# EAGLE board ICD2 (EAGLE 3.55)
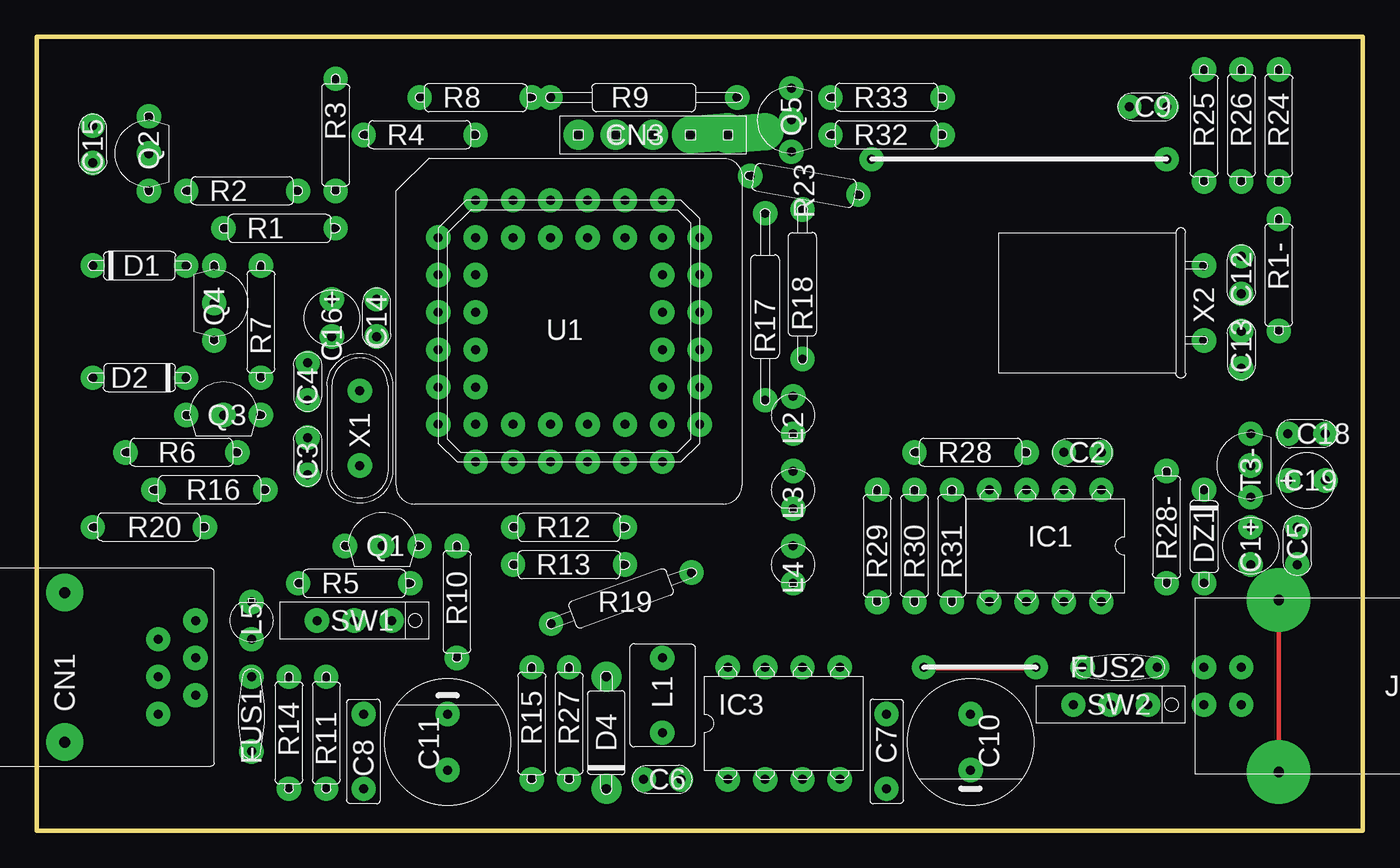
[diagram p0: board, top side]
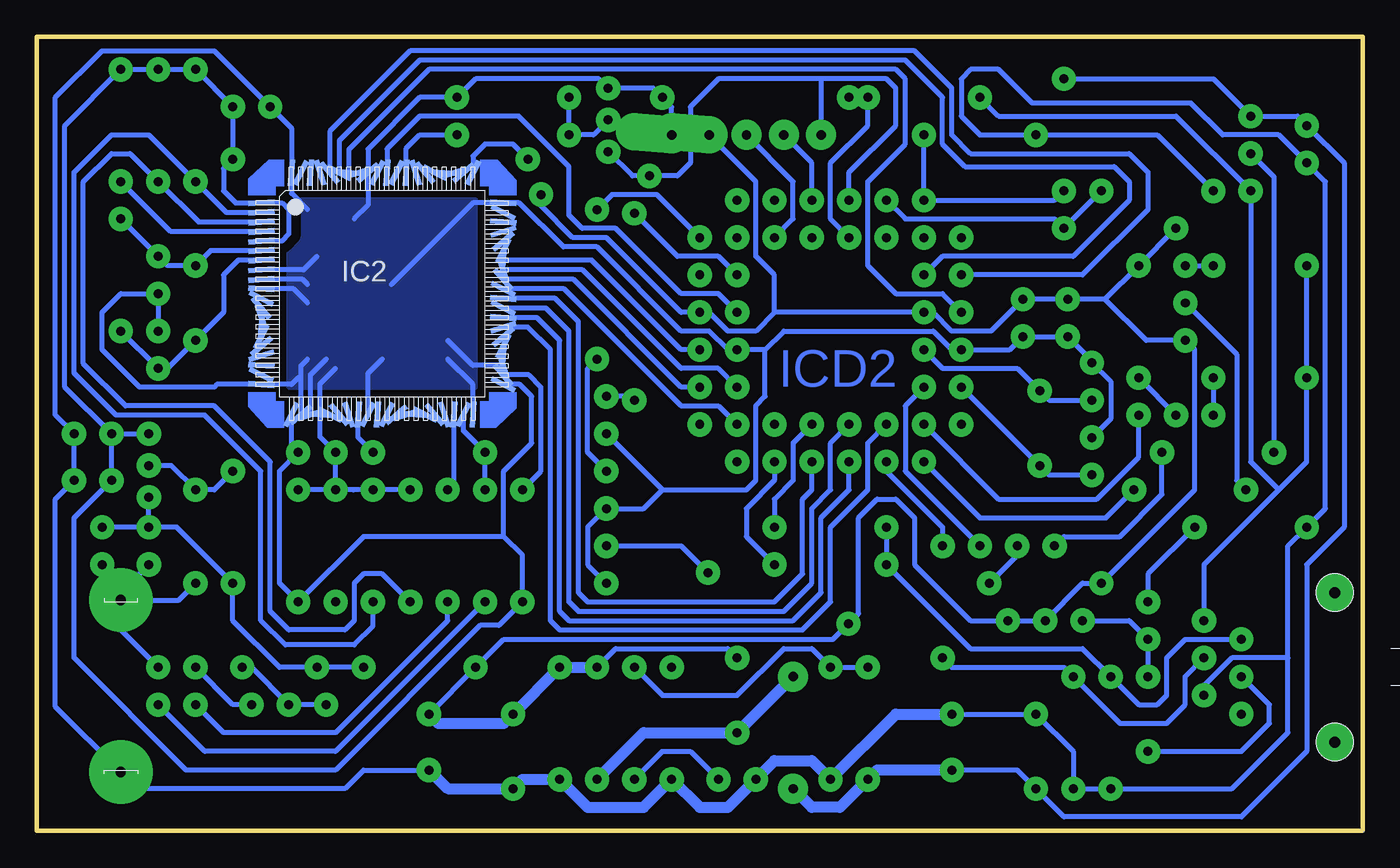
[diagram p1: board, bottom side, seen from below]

Size 90.17 x 53.98 mm. Coordinates in mm from the lower left corner, seen from the top.
Outline: 0,0 0,53.98 90.17,53.98 90.17,0 0,0
Copper layers used: COTE_COM, COTE_SOU

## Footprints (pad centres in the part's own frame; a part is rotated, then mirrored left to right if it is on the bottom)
-2,5-G = drill 0.612 pad 1.651 round:  -1.27,0;  1.27,0
2,5-0 = drill 0.612 pad 1.651 round:  -1.27,0;  1.27,0
5 = drill 0.612 pad 1.651 round:  2.54,0;  -2.54,0
-08-00 = drill 0.612 pad 1.651 round:  -1.905,0;  1.905,0
DUL-6 = drill 0.612 pad 1.651 round:  -1.27,-0.635;  1.27,0.635;  -1.27,1.905;  1.27,3.175;  1.27,-1.905;  -1.27,-3.175 | drill 0.744 pad 2.54 round:  7.62,-5.08;  7.62,5.08
14-05 = drill 0.637 pad 2.032 round:  -3.81,0;  -1.27,0;  1.27,0 | drill 0.637 pad 2.54 offset:  3.81,0;  6.35,0
6,3 = drill 0.612 pad 1.651 round:  3.175,0;  -3.175,0
7,5-1 = drill 0.637 pad 2.032 round:  -3.81,0;  3.81,0
SE-5 = drill 0.612 pad 1.651 round:  -2.54,0;  2.54,0
L-08 = drill 0.612 pad 1.651 round:  0,0;  2.54,0;  5.08,0;  7.62,0;  7.62,7.62;  5.08,7.62;  2.54,7.62;  0,7.62
FP-80 = smd 1.778 x 0.356 rotated 4.8:  -8.223,2.275 | smd 1.778 x 0.356 rotated 4.3:  -8.223,6.175;  -8.223,0.325 | smd 1.778 x 0.356 rotated 4.4:  -8.223,5.525;  -8.223,-6.175 | smd 1.778 x 0.356 rotated 4.5:  -8.223,4.875 | smd 1.778 x 0.356 rotated 4.6:  -8.223,4.225 | smd 1.778 x 0.356 rotated 4.7:  -8.223,3.575;  -8.223,2.925;  8.223,-0.325;  8.223,6.175 | smd 1.778 x 0.356 rotated 4.9:  -8.223,1.625 | smd 1.778 x 0.356 rotated 5:  -8.223,0.975 | smd 1.778 x 0.356 rotated 26.8:  -8.223,-0.325 | smd 1.778 x 0.356 rotated 49.3:  -8.223,-0.975 | smd 1.778 x 0.356 rotated 71.8:  -8.223,-1.625 | smd 1.778 x 0.356 rotated 94.3:  -8.223,-2.275 | smd 1.778 x 0.356 rotated 116.8:  -8.223,-2.925 | smd 1.778 x 0.356 rotated 139.3:  -8.223,-3.575 | smd 1.778 x 0.356 rotated 161.8:  -8.223,-4.225 | smd 1.778 x 0.356 rotated 184.3:  -8.223,-4.875 | smd 1.778 x 0.356 rotated 206.8:  -8.223,-5.525 | smd 0.356 x 1.778 rotated 26.9:  -6.175,-8.223 | smd 0.356 x 1.778 rotated 49.4:  -5.525,-8.223 | smd 0.356 x 1.778 rotated 71.9:  -4.875,-8.223 | smd 0.356 x 1.778 rotated 94.4:  -4.225,-8.223 | smd 0.356 x 1.778 rotated 116.9:  -3.575,-8.223 | smd 0.356 x 1.778 rotated 139.4:  -2.925,-8.223 | smd 0.356 x 1.778 rotated 161.9:  -2.275,-8.223 | smd 0.356 x 1.778 rotated 184.4:  -1.625,-8.223 | smd 0.356 x 1.778 rotated 206.9:  -0.975,-8.223 | smd 0.356 x 1.778 rotated 4.5:  -0.325,-8.223 | smd 0.356 x 1.778 rotated 27:  0.325,-8.223 | smd 0.356 x 1.778 rotated 49.5:  0.975,-8.223 | smd 0.356 x 1.778 rotated 72:  1.625,-8.223 | smd 0.356 x 1.778 rotated 94.5:  2.275,-8.223 | smd 0.356 x 1.778 rotated 117:  2.925,-8.223 | smd 0.356 x 1.778 rotated 139.5:  3.575,-8.223 | smd 0.356 x 1.778 rotated 162:  4.225,-8.223 | smd 0.356 x 1.778 rotated 184.5:  4.875,-8.223 | smd 0.356 x 1.778 rotated 207:  5.525,-8.223 | smd 0.356 x 1.778 rotated 4.6:  6.175,-8.223 | smd 1.778 x 0.356 rotated 27.1:  8.223,-6.175 | smd 1.778 x 0.356 rotated 49.6:  8.223,-5.525 | smd 1.778 x 0.356 rotated 72.1:  8.223,-4.875 | smd 1.778 x 0.356 rotated 94.6:  8.223,-4.225 | smd 1.778 x 0.356 rotated 117.1:  8.223,-3.575 | smd 1.778 x 0.356 rotated 139.6:  8.223,-2.925 | smd 1.778 x 0.356 rotated 162.1:  8.223,-2.275 | smd 1.778 x 0.356 rotated 184.6:  8.223,-1.625 | smd 1.778 x 0.356 rotated 207.1:  8.223,-0.975 | smd 1.778 x 0.356 rotated 27.2:  8.223,0.325 | smd 1.778 x 0.356 rotated 49.7:  8.223,0.975 | smd 1.778 x 0.356 rotated 72.2:  8.223,1.625 | smd 1.778 x 0.356 rotated 94.7:  8.223,2.275 | smd 1.778 x 0.356 rotated 117.2:  8.223,2.925 | smd 1.778 x 0.356 rotated 139.7:  8.223,3.575 | smd 1.778 x 0.356 rotated 162.2:  8.223,4.225 | smd 1.778 x 0.356 rotated 184.7:  8.223,4.875 | smd 1.778 x 0.356 rotated 207.2:  8.223,5.525 | smd 0.356 x 1.778 rotated 27.2:  6.175,8.223 | smd 0.356 x 1.778 rotated 49.7:  5.525,8.223 | smd 0.356 x 1.778 rotated 72.2:  4.875,8.223 | smd 0.356 x 1.778 rotated 94.7:  4.225,8.223 | smd 0.356 x 1.778 rotated 117.2:  3.575,8.223 | smd 0.356 x 1.778 rotated 139.7:  2.925,8.223 | smd 0.356 x 1.778 rotated 162.2:  2.275,8.223 | smd 0.356 x 1.778 rotated 184.7:  1.625,8.223 | smd 0.356 x 1.778 rotated 207.2:  0.975,8.223 | smd 0.356 x 1.778 rotated 4.8:  0.325,8.223 | smd 0.356 x 1.778 rotated 27.3:  -0.325,8.223 | smd 0.356 x 1.778 rotated 49.8:  -0.975,8.223 | smd 0.356 x 1.778 rotated 72.3:  -1.625,8.223 | smd 0.356 x 1.778 rotated 94.8:  -2.275,8.223 | smd 0.356 x 1.778 rotated 117.3:  -2.925,8.223 | smd 0.356 x 1.778 rotated 139.8:  -3.575,8.223 | smd 0.356 x 1.778 rotated 162.3:  -4.225,8.223 | smd 0.356 x 1.778 rotated 184.8:  -4.875,8.223 | smd 0.356 x 1.778 rotated 207.3:  -5.525,8.223 | smd 0.356 x 1.778 rotated 4.9:  -6.175,8.223
B-B2 = drill 0.612 pad 1.651 round:  -1.27,-1.27;  -1.27,1.27;  1.27,-1.27;  1.27,1.27 | drill 0.691 pad 4.318 round:  -3.81,-5.842;  -3.81,5.842
220æH = drill 0.612 pad 1.651 round:  -2.54,0;  2.54,0
D-3 = drill 0.612 pad 1.651 round:  -1.27,0;  1.27,0
D-3SF0 = drill 0.612 pad 1.651 round:  -1.27,0;  1.27,0
92 = drill 0.612 pad 1.651 round:  0,0;  2.54,0;  -2.54,0
 = drill 0.612 pad 1.651 round:  2.159,0;  -2.159,0;  0,0
10-7S = drill 0.612 pad 1.651 round:  -3.81,0;  3.81,0
10-12S = drill 0.612 pad 1.651 round:  6.35,0;  -6.35,0
10 = drill 0.612 pad 1.651 round:  5.08,0;  -5.08,0
ø0#R-1 = drill 0.612 pad 1.651 round:  4.774,1.738;  -4.774,-1.738
ø0#R-1' = drill 0.612 pad 1.651 round:  -0.635,-3.683;  0.635,3.683
-SIL3V = drill 0.612 pad 1.651 round:  0,0;  0,-2.54;  0,2.54
CC-44 = drill 0.612 pad 1.651 round:  2.54,-2.54;  0,-2.54;  7.62,-2.54;  5.08,-2.54;  12.7,-2.54;  10.16,-2.54;  17.78,-2.54;  15.24,-2.54;  15.24,0;  12.7,0;  10.16,0;  7.62,0;  5.08,0;  2.54,0;  2.54,-5.08;  0,-5.08;  2.54,-7.62;  0,-7.62;  2.54,-10.16;  0,-10.16;  2.54,-12.7;  0,-12.7;  2.54,-15.24;  0,-15.24;  7.62,-15.24;  5.08,-15.24;  5.08,-17.78;  2.54,-17.78;  10.16,-17.78;  7.62,-17.78;  12.7,-15.24;  10.16,-15.24;  15.24,-17.78;  12.7,-17.78;  17.78,-15.24;  15.24,-15.24;  17.78,-12.7;  15.24,-12.7;  17.78,-10.16;  15.24,-10.16;  17.78,-7.62;  15.24,-7.62;  17.78,-5.08;  15.24,-5.08
ARTZ = drill 0.612 pad 1.651 round:  -2.54,0;  2.54,0
ARTZ-C = drill 0.612 pad 1.651 round:  2.54,0;  -2.54,0

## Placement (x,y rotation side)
C1  10æ  [-2,5-G]  82.55,19.37 270 top
C2  104  [2,5-0]  71.12,25.72 180 top
C3  22p  [2,5-0]  18.41,25.46 90 top
C4  22p  [2,5-0]  18.41,30.54 90 top
C5  104  [2,5-0]  85.72,19.37 270 top
C6  47p  [2,5-0]  42.55,3.49 180 top
C7  1æ  [5]  57.78,5.4 270 top
C8  1æ  [5]  22.23,5.4 90 top
C9  104  [2,5-0]  75.56,49.21 180 top
C10  220æ  [-08-00]  63.5,6.03 270 top
C11  470æ/16V  [-08-00]  27.94,6.03 90 top
C12  22p  [2,5-0]  81.91,37.78 270 top
C13  22p  [2,5-0]  81.91,32.7 90 top
C14  104  [2,5-0]  23.11,34.86 270 top
C15  104  [2,5-0]  3.81,46.67 270 top
C16  10æ  [-2,5-G]  20.07,34.86 270 top
C18  104  [2,5-0]  86.36,26.99 0 top
C19  10æ  [-2,5-G]  86.36,23.81 0 top
CN1  ISP  [DUL-6]  9.52,11.11 180 top
CN3  PROG  [14-05]  40.64,47.31 0 top
D1  BAT85  [6,3]  6.98,38.42 0 top
D2  BAT85  [6,3]  6.98,30.8 180 top
D4  BYV  [7,5-1]  38.73,6.67 90 top
DZ1  3V9  [6,3]  79.38,20 270 top
FUS1  100mA  [SE-5]  14.61,7.94 270 top
FUS2  200mA  [SE-5]  73.66,11.11 180 top
IC1  24LC16  [L-08]  72.39,23.18 180 top
IC2  CY7C64613  [FP-80]  66.67,36.51 0 bottom
IC3  MAX630  [L-08]  46.99,3.49 0 top
J4  USB  [B-B2]  80.65,9.84 180 top
L1  470æ  [220æH]  42.55,9.21 270 top
L2  FAIL  [D-3]  51.44,28.26 90 top
L3  RUN  [D-3]  51.44,23.18 90 top
L4  ON  [D-3]  51.44,18.1 90 top
L5  ISP  [D-3SF0]  14.61,14.29 270 top
Q1  547  [92]  23.5,19.37 0 top
Q2  557  [92]  7.62,46.04 90 top
Q3  547  [92]  12.7,28.26 0 top
Q4  557  [92]  12.06,35.88 270 top
Q5  547  []  51.31,48.32 90 top
R1  4K7  [10-7S]  16.51,40.96 0 top
R1-  1M  [10-7S]  84.45,37.78 270 top
R2  4K7  [10-7S]  13.97,43.5 180 top
R3  6K8  [10-7S]  20.32,47.31 270 top
R4  2K2  [10-7S]  26.04,47.31 180 top
R5  100K  [10-7S]  21.59,16.83 0 top
R6  47K  [10-7S]  9.84,25.72 180 top
R7  22K  [10-7S]  15.24,34.61 270 top
R8  6K8  [10-7S]  29.84,49.85 0 top
R9  2K2  [10-12S]  41.27,49.85 0 top
R10  330R  [10-7S]  28.57,15.56 270 top
R11  4K7  [10-7S]  19.69,6.67 270 top
R12  330R  [10-7S]  36.2,20.64 0 top
R13  330R  [10-7S]  36.2,18.1 0 top
R14  4K7  [10-7S]  17.14,6.67 270 top
R15  137K  [10-7S]  33.66,7.3 270 top
R16  22K  [10-7S]  11.75,23.18 180 top
R17  1K5  [10-12S]  49.53,35.62 90 top
R18  1K5  [10]  52.07,37.15 90 top
R19  1K5  [ø0#R-1]  39.75,15.81 0 top
R20  75R  [10-7S]  7.62,20.64 180 top
R23  10K  [ø0#R-1']  52.2,43.88 90 top
R24  10K  [10-7S]  84.45,47.94 270 top
R25  1K  [10-7S]  79.38,47.94 270 top
R26  1K  [10-7S]  81.91,47.94 270 top
R27  15K  [10-7S]  36.2,7.3 270 top
R28  1K5  [10-7S]  63.5,25.72 180 top
R28-  150R  [10-7S]  76.84,20.64 90 top
R29  10K  [10-7S]  57.15,19.37 270 top
R30  22R  [10-7S]  59.69,19.37 90 top
R31  22R  [10-7S]  62.23,19.37 90 top
R32  1K  [10-7S]  57.78,47.31 180 top
R33  4K7  [10-7S]  57.78,49.85 180 top
SW1  PWR  [-SIL3V]  21.59,14.29 90 top
SW2  USB  [-SIL3V]  73.03,8.57 90 top
T3-  547  []  82.55,24.83 90 top
U1  PIC16F877-L  [CC-44]  27.3,42.86 0 top
U$7  [ILAND]  22.86,26.99 0 top
U$8  [ILAND]  67.31,26.99 180 top
X1  20M  [ARTZ]  21.97,27.37 90 top
X2  12M  [ARTZ-C]  79.38,35.88 90 top

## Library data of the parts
C1-C16 C18 C19 = CONDO
CN1 J4 = CONNEC
CN3 = CONN-HE
D1 D2 D4 DZ1 FUS1 FUS2 L1 Q1-Q5 R1 R1- R2-R18 R20 R24-R28 R28- R29-R33 SW1 SW2 T3- X1 X2 = EAGLE
IC1 IC3 U1 = INTEL
IC2 = SMD-MIC
L2-L5 = OPTO
R19 = Rotation
R23 = RESISTAN
U$7 U$8 = BOITIER

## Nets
0V: C1. C2. C3. C4. C5. C6. C7. C8. C9. C10. C11. C12. C13. C14. C15. C16. C18. C19. CN1. CN3. DZ1. IC1. IC2. IC3. J4. L2. L3. L4. Q5. R2. R4. R9. R11. R14. R20. R27. R33. U1.
3V9: DZ1. R28-. T3-.
+3V3: C2. C9. C18. C19. IC1. IC2. R24. R25. R26. R29. T3-.
+5V: C1. C5. C7. C10. C14. C16. CN3. FUS2. IC3. L1. Q4. R1. R5. R7. R19. R23. R28-. SW1. T3-. U1.
+5V_ISP: CN1. FUS1.
+5V_USB: FUS2. SW2.
+13V: C8. C11. C15. D4. Q2. R3. R15.
+D+: J4. R30.
+LED8ISP: FUS1. L5. SW1.
-D-: J4. R31.
-LED: L5. R20.
B_Q5: Q5. R32. R33.
B_T2: Q1. R5.
B_T3: Q2. R6.
B_T4: Q4. R16.
B_T5: Q3. R7.
C_T1: Q1. R6.
C_T2: D2. Q3.
C_T4: D1. Q4.
CX: C6. IC3.
DAT_ISP: CN1. R12. R13. R14.
DAT_RC5: R13. U1.
DISCON/: IC2. R28.
FAIL+: L2. R17.
FB_1V1: IC3. R15. R27.
INT_RB0: IC2. U1.
LED2+1: L4. R19.
LX1: D4. IC3. L1.
MCLR/: CN3. Q5. R23. U1.
N$1: J4. SW2.
N$5: C3. U1. X1.
N$6: C4. U1. X1.
PC0: IC2. R32.
RA0_RST: R8. R9. U1.
RA1: R1. R2. U1.
RA3_VPP: R3. R4. U1.
RB2_FAIL: R17. U1.
RB3_RUN: R18. U1.
RB6_CLK: CN3. U1.
RB7_DAT: CN3. U1.
RC0_: Q1. U1.
RC1_: R16. U1.
RC2_: Q3. U1.
RC3_SCK: R10. U1.
RC4DAT: R12. U1.
RD0: IC2. U1.
RD1: IC2. U1.
RD2: IC2. U1.
RD3: IC2. U1.
RD4: IC2. U1.
RD5: IC2. U1.
RD6: IC2. U1.
RD7: IC2. U1.
RE0: IC2. U1.
RE1: IC2. U1.
RE2: IC2. U1.
RST/: IC2. R29.
RUN+: L3. R18.
SCK_ISP: CN1. R10. R11.
SCL: IC1. IC2. R25.
SDA: IC1. IC2. R26.
USBD+: IC2. R28. R30.
USBD-: IC2. R31.
VPP: CN1. D1. D2. Q2. R8.
WAKEUP: IC2. R24.
XIN: C12. IC2. R1-. X2.
XOU: C13. IC2. R1-. X2.

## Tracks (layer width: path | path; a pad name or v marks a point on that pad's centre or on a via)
0V
  COTE_COM 0.305: J4. 84.45,15.68
  COTE_SOU 0.356: 40.64,32.7 39.37,33.97 29.21,33.97 27.94,32.7 27.3,32.7 24,32.7 C14. C16. 18.41,31.94 C4. 17.14,30.54 17.14,28 C3. | 40.64,32.7 42.55,32.7 43.18,32.7 44.45,33.97 46.36,33.97 52.07,39.69 54.36,39.69 57.36,42.69 58.45,42.69 60.5,42.69 66.04,37.15 | 69.85,23.18 72.39,23.18 | 67.94,23.18 69.85,23.18 | 67.94,23.18 67.31,23.18 64.77,23.18 | 67.94,23.18 68.66,23.18 | 84.45,15.68 84.45,13.65 81.91,11.11 | 58.45,31.64 60.53,31.64 62.23,33.34 | 60.5,28.29 60.5,30.34 62.23,32.07 | 67.65,28.29 67.65,31.09 66.67,32.07 | 74.9,36.84 72.72,36.84 71.75,35.88 | 74.9,37.49 72.09,37.49 71.75,37.15 | 74.9,38.14 72.03,38.14 71.12,39.05 | 71.75,42.23 72.85,43.32 IC2. 72.85,47.77 C9. 78.11,53.02 85.72,53.02 88.9,49.85 88.9,28.26 C18. C19. 88.9,22.54 88.9,8.45 J4. 83.31,2.86 69.22,2.86 67.94,4.13 C10. | 68.58,41.59 67.65,42.52 67.65,44.74 67.65,46.33 64.14,49.85 61.59,49.85 60.33,51.12 51.94,51.12 51.31,50.48 48.26,50.48 47.62,49.85 46.99,49.21 CN3. | 72.2,28.29 72.2,31.62 71.75,32.07 | 69.85,31.43 70.9,30.38 70.9,28.29 70.9,26.77 C2. 69.85,23.18 | C11. 22.23,7.94 19.69,5.4 R11. R14. 8.89,2.86 5.08,6.67 5.08,11.75 | R2. 13.97,47.31 R4. 26.04,47.31 27.3,48.58 27.3,51.12 26.67,51.75 24.77,51.75 22.48,49.47 11.68,49.47 9.52,47.31 5.72,47.31 C15. 2.54,44.13 2.54,21.91 R20. 5.08,19.37 5.08,11.75 | 84.45,15.68 80.52,15.68 79.38,16.83 | 40.64,32.7 40.64,29.53 41.27,28.89 41.27,23.81 41.91,23.18 47.62,23.18 | 51.44,16.83 52.7,18.1 52.7,20.64 51.44,21.91 48.9,21.91 47.62,23.18 | 71.55,28.29 71.55,31 70.48,32.07 | 72.39,30.8 72.85,30.34 74.9,30.34 77.93,30.34 78.11,30.16 83.19,30.16 85.72,32.7 85.72,35.24 84.45,36.51 C12. C13.
  COTE_SOU 0.356: C1. 83.82,16.83 83.82,16.32 84.45,15.68 | 84.45,15.68 84.45,16.83 C5. | 47.62,23.18 51.44,26.99 | 10.8,9.21 10.8,9.84 8.89,11.75 5.08,11.75
  COTE_SOU 0.762: C10. 62.23,2.86 57.78,2.86 57.15,3.49 54.61,3.49 52.7,1.59 48.9,1.59 46.99,3.49 45.09,1.59 43.18,1.59 C6. 40.01,4.76 37.47,4.76 R27. 31.75,7.94 C11.
  pour COTE_SOU (isolate 0.635, no thermals): 60.33,30.16 60.33,42.86 73.03,42.86 73.03,30.16
3V9
  COTE_SOU 0.356: T3-. 81.03,24.83 DZ1. 78.11,23.18 R28-.
+3V3  (via drill 0.61 pad 1.65)
  COTE_COM 0.305: v76.84,45.66 v56.77,45.66
  COTE_SOU 0.356: 74.9,40.09 73.51,40.09 73.03,40.58 73.03,42.23 73.48,42.69 74.9,42.69 76.66,42.69 77.47,43.5 77.47,45.02 v76.84,45.66 76.84,49.21 79.38,51.75 81.91,51.75 84.45,51.75 88.27,47.94 88.27,30.16 85.09,26.99 | 72.85,28.29 72.85,26.18 72.39,25.72 73.66,24.45 73.66,16.83 IC1. 67.94,20 58.42,20 | 85.09,26.99 85.09,23.81 87.63,21.27 87.63,11.75 80.01,4.13 69.85,4.13 60.01,13.97 58.74,13.97 R29. 57.15,18.73 58.42,20 | 85.09,26.99 82.55,26.99 | 58.45,30.34 57.33,30.34 56.52,29.53 56.52,26.35 58.42,24.45 58.42,20 | 60.5,44.74 60.5,45.86 59.69,46.67 57.78,46.67 v56.77,45.66
+5V  (via drill 0.61 pad 1.65)
  COTE_COM 0.406: v60.33,11.11 v67.94,11.11
  COTE_SOU 0.356: 52.07,11.11 50.8,12.38 43.18,12.38 42.55,11.75 | 12.7,40.96 15.24,38.42 17.53,36.13 | 40.01,35.24 41.27,33.97 43.18,33.97 44.45,35.24 45.09,35.24 46.36,35.24 51.44,40.32 53.72,40.32 55.88,42.48 55.88,43.24 | 40.01,35.24 29.84,35.24 29.21,35.24 27.94,33.97 25.27,33.97 23.11,36.13 20.07,36.13 17.53,36.13 | 82.55,20.64 80.65,20.64 76.84,16.83 76.84,14.29 73.66,11.11 FUS2. v67.94,11.11 | 82.55,20.64 82.55,22.67 | 82.55,20.64 85.72,20.64 | 17.53,36.13 14.73,33.34 12.06,33.34 11.43,32.7 11.43,23.18 17.78,16.83 19.05,16.83 21.59,14.29 24.13,14.29 26.67,14.29 30.48,18.1 30.48,21.27 31.75,22.54 33.02,22.54 34.29,21.27 34.29,14.76 R19. 36.03,13.02 58.42,13.02 v60.33,11.11 63.5,7.94 | 40.01,35.24 40.01,37.78 41.27,39.05 41.27,44.13 44.45,47.31
  COTE_SOU 0.762: 52.07,11.11 54.61,11.11 C7. 58.42,7.3 62.87,7.3 63.5,7.94
+5V_ISP
  COTE_SOU 0.356: 8.26,10.48 6.35,8.57 6.35,7.3 8.26,5.4 FUS1.
+5V_USB
  COTE_SOU 0.356: 76.2,11.11 75.56,11.11 73.03,8.57 SW2.
+13V
  COTE_SOU 0.356: 27.94,4.13 23.5,4.13 C8. 20.32,0.95 8.26,0.95 3.81,5.4 3.81,18.1 1.27,20.64 1.27,45.4 3.81,47.94 4.45,48.58 7.62,48.58 10.16,51.12 20.32,51.12
  COTE_SOU 0.762: 38.73,2.86 37.47,1.59 35.56,1.59 R15. 33.02,4.13 27.94,4.13
+D+
  COTE_SOU 0.356: 59.69,15.56 69.85,5.4 78.74,5.4 81.91,8.57
+LED8ISP
  COTE_SOU 0.356: 14.61,10.48 L5. 15.88,14.29 SW1.
-D-
  COTE_SOU 0.356: 62.23,15.56 62.23,14.29 69.85,6.67 77.47,6.67 79.38,8.57
-LED
  COTE_SOU 0.356: 14.61,15.56 14.61,17.46 11.43,20.64
B_Q5
  COTE_SOU 0.356: R33. R32. 52.32,47.31 Q5.
B_T2
  COTE_SOU 0.356: 23.5,19.37 23.5,18.73 R5.
B_T3
  COTE_SOU 0.356: R6. 6.03,44.45 7.62,46.04
B_T4
  COTE_SOU 0.356: 12.06,35.88 8.57,32.38 8.57,23.81 R16.
B_T5
  COTE_SOU 0.356: R7. 12.7,28.26
C_T1
  COTE_SOU 0.356: 13.65,25.72 13.65,22.86 16.51,20 20.32,20 Q1.
C_T2
  COTE_SOU 0.356: D2. Q3.
C_T4
  COTE_SOU 0.356: Q4. 10.16,38.42
CX
  COTE_SOU 0.356: 43.81,3.49 45.72,5.4 47.62,5.4 49.53,3.49
DAT_ISP
  COTE_SOU 0.356: 32.39,20.64 32.39,18.1 26.67,12.38 19.05,12.38 17.14,10.48 15.24,8.57 13.97,8.57 13.34,9.21 13.34,11.75 12.06,13.02 8.26,13.02
DAT_RC5
  COTE_SOU 0.356: 40.01,25.08 40.01,23.81 41.91,21.91 41.91,20 R13.
DISCON/
  COTE_SOU 0.356: 68.3,28.29 68.3,26.71 67.31,25.72
FAIL+
  COTE_SOU 0.356: R17. 49.78,29.53 L2.
FB_1V1
  COTE_SOU 0.356: 49.53,11.11 47.62,9.21 42.55,9.21 39.37,12.38 37.47,12.38 36.2,11.11 33.66,11.11
INT_RB0
  COTE_SOU 0.356: 42.55,35.24 43.81,36.51 46.36,36.51 50.8,40.96 53.09,40.96 53.98,41.85 53.98,45.15 57.4,48.58 64.14,48.58 66.35,46.36 66.35,44.74
LED2+1
  COTE_SOU 0.356: 44.52,17.55 46.34,19.37 L4.
LX1
  COTE_SOU 0.762: 52.07,3.49 48.9,6.67 L1. D4.
MCLR/
  COTE_SOU 0.356: 34.92,42.86 34.92,44.77 31.75,47.94 31.75,50.48 32.39,51.12 36.83,51.12 | 51.31,46.16 49.66,44.51 R23. 46.61,44.51 45.72,45.4 45.72,49.21 43.81,51.12 36.83,51.12 | 36.83,51.12 36.83,47.31
N$1
  COTE_SOU 0.356: 75.56,8.57 76.84,8.57 79.38,11.11
N$5
  COTE_SOU 0.356: 27.3,30.16 21.97,24.83 21.34,24.19 18.41,24.19
N$6
  COTE_SOU 0.356: 29.84,32.7 28.57,31.43 23.5,31.43 X1. 21.34,29.27 18.41,29.27
PC0
  COTE_SOU 0.356: 65.05,44.74 65.05,46.39 64.14,47.31 61.59,47.31
RA0_RST
  COTE_SOU 0.356: 34.92,40.32 36.2,41.59 36.2,45.4 33.66,47.94 R8. R9.
RA1
  COTE_SOU 0.356: 32.39,42.86 31.12,41.59 20.96,41.59 R1. 17.78,43.5
RA3_VPP
  COTE_SOU 0.356: 29.84,47.31 29.84,42.86 20.96,42.86 R3.
RB2_FAIL
  COTE_SOU 0.356: U1. 43.81,39.05 46.61,39.05 49.53,41.97
RB3_RUN
  COTE_SOU 0.356: 52.07,42.23 51.05,43.24 48.01,43.24 45.09,40.32
RB6_CLK
  COTE_SOU 0.356: 40.01,40.32 38.73,41.59 38.73,44.13 41.91,47.31
RB7_DAT
  COTE_SOU 0.356: 37.47,42.86 37.47,45.4 39.37,47.31
RC0_
  COTE_SOU 0.356: 29.84,30.16 31.12,28.89 31.12,24.45 26.04,19.37
RC1_
  COTE_SOU 0.356: 29.84,25.08 26.04,21.27 17.46,21.27 15.56,23.18
RC2_
  COTE_SOU 0.356: 29.84,27.62 24.77,22.54 18.1,22.54 15.24,25.4 15.24,28.26
RC3_SCK
  COTE_SOU 0.356: 32.39,25.08 32.39,24.45 28.57,20.64 28.57,19.37
RC4DAT
  COTE_SOU 0.356: 37.47,27.62 38.73,26.35 38.73,23.81 40.01,22.54 R12.
RD0
  COTE_SOU 0.356: 32.39,27.62 33.66,26.35 33.66,23.18 36.2,20.64 36.2,15.56 38.1,13.65 54.61,13.65 55.25,14.29 55.25,32.7 56.78,34.24 58.45,34.24
RD1
  COTE_SOU 0.356: 34.92,25.08 34.92,23.18 36.83,21.27 36.83,16.19 38.73,14.29 53.98,14.29 54.61,14.92 54.61,33.34 56.16,34.89 58.45,34.89
RD2
  COTE_SOU 0.356: 34.92,27.62 36.2,26.35 36.2,23.18 37.47,21.91 37.47,16.83 39.37,14.92 53.34,14.92 53.98,15.56 53.98,33.97 55.54,35.54 58.45,35.54
RD3
  COTE_SOU 0.356: 37.47,25.08 37.47,23.18 38.1,22.54 38.1,17.46 40.01,15.56 52.7,15.56 53.34,16.19 53.34,34.61 54.92,36.19 58.45,36.19
RD4
  COTE_SOU 0.356: 42.55,27.62 43.81,28.89 46.36,28.89 54.3,36.84 58.45,36.84
RD5
  COTE_SOU 0.356: 45.09,30.16 46.36,30.16 53.68,37.49 58.45,37.49
RD6
  COTE_SOU 0.356: 42.55,30.16 43.81,31.43 46.36,31.43 53.06,38.14 58.45,38.14
RD7
  COTE_SOU 0.356: 45.09,32.7 46.36,32.7 52.44,38.79 58.45,38.79
RE0
  COTE_SOU 0.356: 70.25,44.74 70.25,47.54 64.77,53.02 30.48,53.02 27.94,50.48 27.94,47.31 26.67,46.04 15.88,46.04 14.61,44.77 14.61,42.23 19.05,37.78 27.3,37.78
RE1
  COTE_SOU 0.356: 29.84,37.78 28.57,39.05 19.69,39.05 15.88,42.86 15.88,44.13 16.89,45.15 27.05,45.15 28.57,46.67 28.57,49.85 31.12,52.39 64.14,52.39 69.6,46.92 69.6,44.74
RE2
  COTE_SOU 0.356: 27.3,35.24 28.57,36.51 31.75,36.51 33.66,38.42 33.66,44.13 31.12,46.67 31.12,51.12 31.75,51.75 63.5,51.75 68.95,46.3 68.95,44.74
RST/
  COTE_SOU 0.356: 58.45,30.99 56.7,30.99 55.88,30.16 55.88,24.45 57.15,23.18
RUN+
  COTE_SOU 0.356: L3. 52.7,25.72 52.7,31.43 R18.
SCK_ISP
  COTE_SOU 0.356: R10. 27.94,11.11 20.32,11.11 19.69,10.48 16.51,7.3 13.34,7.3 12.06,8.57 12.06,10.48 10.8,11.75
SCL
  COTE_SOU 0.356: 67.31,15.56 67.31,13.91 68.58,12.64 73.28,12.64 74.93,14.29 74.93,24.45 78.74,28.26 84.77,28.26 87.63,31.12 87.63,44.77 85.09,47.31 82.55,47.31 R25. 77.28,42.04 74.9,42.04
SDA
  COTE_SOU 0.356: 64.77,15.56 66.67,17.46 67.94,17.46 68.58,16.83 68.58,14.29 69.22,13.65 73.03,13.65 74.3,14.92 74.3,25.08 78.11,28.89 84.14,28.89 87,31.75 87,44.13 85.09,46.04 83.82,46.04 R26. 79.17,41.39 74.9,41.39
USBD+
  COTE_SOU 0.356: R30. R28. 61.15,27.18 61.15,28.29
USBD-
  COTE_SOU 0.356: 61.8,28.29 61.8,23.61 R31.
VPP
  COTE_SOU 0.356: 26.04,49.85 24.77,48.58 12.7,48.58 Q2. 7.62,25.08 5.72,23.18 | 5.72,23.18 3.81,25.08 3.81,30.8 D1. | 10.8,14.29 10.8,18.1 5.72,23.18
WAKEUP
  COTE_SOU 0.356: 74.9,40.74 81.06,40.74 R24.
XIN
  COTE_SOU 0.356: 74.9,39.44 78.36,39.44 79.38,38.42 81.28,38.42 81.91,39.05 84.45,41.59
XOU
  COTE_SOU 0.356: 74.9,38.79 76.47,38.79 77.47,37.78 77.47,35.24 X2. 81.28,31.43 81.91,31.43 R1-.

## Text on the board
COTE_SOU: ICD2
